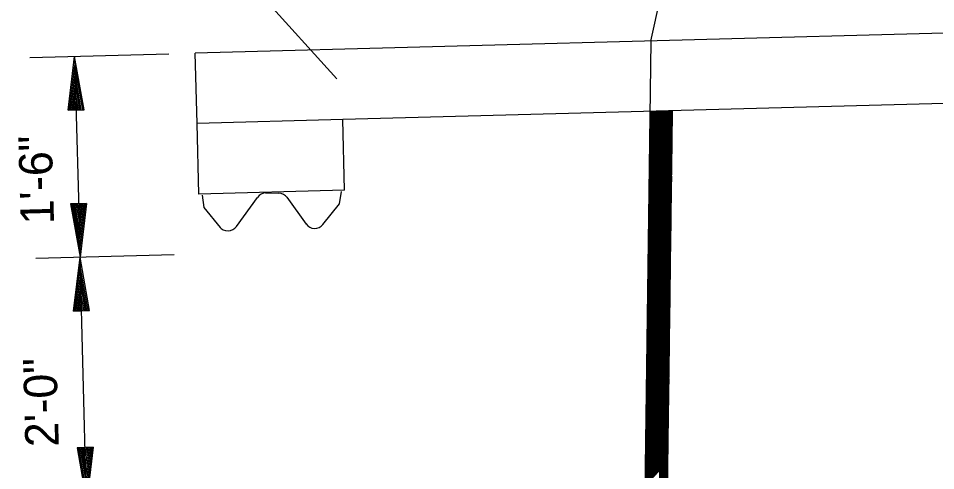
# Model space of a CAD drawing. Extents: x 1929624 to 1935547, y 596315 to 605721.
# Drawn here: x 1932251.9 to 1932416.4, y 600610.8 to 600691.9 of the extents above; entities that cross this region are included whole.
import ezdxf

# ---------------------------------------------------------------- set-up
doc = ezdxf.new("R2010")
doc.units = 0
doc.layers.add('Default', color=7, linetype='Continuous')

msp = doc.modelspace()

# ---------------------------------------------------------------- linework, layer by layer
at = {"layer": 'Default'}
for p, q in [((1932365.29, 600687.8), (1932409.04, 600885.31)), ((1932308.96, 600681.05), (1932287.75, 600704.49)), ((1932365.29, 600687.8), (1932362.18, 600451.38)), ((1932283.91, 600673.01), (1932283.58, 600685.61)), ((1932278.83, 600685.48), (1932253.92, 600684.81)), ((1932260.78, 600675.39), (1932261.96, 600685.03)), ((1932261.96, 600685.03), (1932262.93, 600649.04)), ((1932263.66, 600675.47), (1932261.96, 600685.03)), ((1932261.02, 600675.4), (1932262, 600683.45)), ((1932263.42, 600675.47), (1932262, 600683.45)), ((1932261.26, 600675.41), (1932262.05, 600681.79)), ((1932263.15, 600675.46), (1932262.05, 600681.79)), ((1932261.5, 600675.41), (1932262.09, 600680.18)), ((1932262.91, 600675.45), (1932262.09, 600680.18)), ((1932261.74, 600675.42), (1932262.13, 600678.55)), ((1932262.67, 600675.45), (1932262.13, 600678.55)), ((1932463.02, 600677.82), (1932310.04, 600673.72)), ((1932261.98, 600675.43), (1932262.18, 600676.97)), ((1932262.43, 600675.44), (1932262.18, 600676.97)), ((1932260.78, 600675.39), (1932263.66, 600675.47)), ((1932365.13, 600675.19), (1932366.85, 600610.85)), ((1932365.18, 600675.2), (1932366.9, 600610.9)), ((1932365.23, 600675.2), (1932366.95, 600610.96)), ((1932365.28, 600675.2), (1932367, 600611.01)), ((1932365.33, 600675.2), (1932367.05, 600611.06)), ((1932365.38, 600675.2), (1932367.1, 600611.11)), ((1932365.43, 600675.2), (1932367.14, 600611.17)), ((1932365.48, 600675.2), (1932367.19, 600611.22)), ((1932365.53, 600675.21), (1932367.24, 600611.27)), ((1932365.58, 600675.21), (1932367.29, 600611.32)), ((1932365.63, 600675.21), (1932367.34, 600611.38)), ((1932365.68, 600675.21), (1932367.39, 600611.43)), ((1932365.73, 600675.21), (1932367.44, 600611.48)), ((1932365.78, 600675.21), (1932367.48, 600611.53)), ((1932365.83, 600675.21), (1932367.53, 600611.59)), ((1932365.88, 600675.21), (1932367.58, 600611.64)), ((1932365.93, 600675.22), (1932367.63, 600611.69)), ((1932365.98, 600675.22), (1932367.68, 600611.74)), ((1932366.03, 600675.22), (1932367.73, 600611.8)), ((1932366.08, 600675.22), (1932367.78, 600611.85)), ((1932366.13, 600675.22), (1932367.82, 600611.9)), ((1932366.18, 600675.22), (1932367.87, 600611.95)), ((1932369.13, 600675.3), (1932366.19, 600451.33)), ((1932366.23, 600675.22), (1932367.92, 600612)), ((1932366.28, 600675.23), (1932367.97, 600612.06)), ((1932366.32, 600675.23), (1932368.02, 600612.11)), ((1932366.37, 600675.23), (1932368.07, 600612.16)), ((1932366.42, 600675.23), (1932368.12, 600612.21)), ((1932366.47, 600675.23), (1932368.17, 600612.27)), ((1932366.52, 600675.23), (1932368.21, 600612.32)), ((1932366.57, 600675.23), (1932368.26, 600612.37)), ((1932366.62, 600675.23), (1932368.31, 600612.52)), ((1932366.67, 600675.24), (1932368.32, 600613.77)), ((1932366.72, 600675.24), (1932368.34, 600615.02)), ((1932366.77, 600675.24), (1932368.36, 600616.27)), ((1932366.82, 600675.24), (1932368.37, 600617.53)), ((1932366.87, 600675.24), (1932368.39, 600618.78)), ((1932366.92, 600675.24), (1932368.41, 600620.03)), ((1932366.97, 600675.24), (1932368.42, 600621.28)), ((1932367.02, 600675.25), (1932368.44, 600622.53)), ((1932367.07, 600675.25), (1932368.46, 600623.78)), ((1932367.12, 600675.25), (1932368.47, 600625.03)), ((1932367.17, 600675.25), (1932368.49, 600626.28)), ((1932367.22, 600675.25), (1932368.51, 600627.53)), ((1932367.27, 600675.25), (1932368.52, 600628.78)), ((1932367.32, 600675.25), (1932368.54, 600630.04)), ((1932367.37, 600675.25), (1932368.55, 600631.29)), ((1932367.42, 600675.26), (1932368.57, 600632.54)), ((1932367.47, 600675.26), (1932368.59, 600633.79)), ((1932367.52, 600675.26), (1932368.6, 600635.04)), ((1932367.57, 600675.26), (1932368.62, 600636.29)), ((1932367.62, 600675.26), (1932368.64, 600637.54)), ((1932367.67, 600675.26), (1932368.65, 600638.79)), ((1932367.72, 600675.26), (1932368.67, 600640.04)), ((1932367.77, 600675.27), (1932368.69, 600641.3)), ((1932367.82, 600675.27), (1932368.7, 600642.55)), ((1932367.87, 600675.27), (1932368.72, 600643.8)), ((1932367.92, 600675.27), (1932368.74, 600645.05)), ((1932367.97, 600675.27), (1932368.75, 600646.3)), ((1932368.02, 600675.27), (1932368.77, 600647.55)), ((1932368.07, 600675.27), (1932368.78, 600648.8)), ((1932368.12, 600675.27), (1932368.8, 600650.05)), ((1932368.17, 600675.28), (1932368.82, 600651.3)), ((1932368.22, 600675.28), (1932368.83, 600652.55)), ((1932368.27, 600675.28), (1932368.85, 600653.81)), ((1932368.32, 600675.28), (1932368.87, 600655.06)), ((1932368.37, 600675.28), (1932368.88, 600656.31)), ((1932368.42, 600675.28), (1932368.9, 600657.56)), ((1932368.47, 600675.28), (1932368.92, 600658.81)), ((1932368.52, 600675.29), (1932368.93, 600660.06)), ((1932368.57, 600675.29), (1932368.95, 600661.31)), ((1932368.62, 600675.29), (1932368.97, 600662.56)), ((1932368.67, 600675.29), (1932368.98, 600663.81)), ((1932368.72, 600675.29), (1932369, 600665.07)), ((1932368.77, 600675.29), (1932369.02, 600666.32)), ((1932368.82, 600675.29), (1932369.03, 600667.57)), ((1932368.87, 600675.3), (1932369.05, 600668.82)), ((1932368.92, 600675.3), (1932369.06, 600670.07)), ((1932368.97, 600675.3), (1932369.08, 600671.32)), ((1932369.02, 600675.3), (1932369.1, 600672.57)), ((1932369.07, 600675.3), (1932369.11, 600673.82)), ((1932369.12, 600675.3), (1932369.13, 600675.07)), ((1932310.04, 600673.72), (1932283.91, 600673.01)), ((1932284.25, 600660.37), (1932283.91, 600673.01)), ((1932310.38, 600661.07), (1932310.04, 600673.72)), ((1932365.09, 600672.7), (1932366.76, 600610.75)), ((1932365.11, 600673.96), (1932366.8, 600610.8)), ((1932365.08, 600671.45), (1932366.71, 600610.69)), ((1932365.06, 600670.2), (1932366.66, 600610.64)), ((1932365.03, 600667.7), (1932366.56, 600610.54)), ((1932365.04, 600668.95), (1932366.61, 600610.59)), ((1932365.01, 600666.45), (1932366.51, 600610.49)), ((1932364.99, 600665.2), (1932366.46, 600610.43)), ((1932364.96, 600662.7), (1932366.37, 600610.33)), ((1932364.98, 600663.95), (1932366.42, 600610.38)), ((1932310.38, 600661.07), (1932284.25, 600660.37)), ((1932364.94, 600661.45), (1932366.32, 600610.28)), ((1932284.83, 600660.17), (1932285.16, 600657.99)), ((1932290.96, 600654.57), (1932294.74, 600659.76)), ((1932296.2, 600660.57), (1932298.56, 600660.54)), ((1932300.02, 600659.81), (1932303.46, 600655)), ((1932309.44, 600658.65), (1932309.79, 600660.82)), ((1932364.93, 600660.19), (1932366.27, 600610.22)), ((1932264.11, 600658.68), (1932261.23, 600658.6)), ((1932261.23, 600658.6), (1932262.93, 600649.04)), ((1932261.47, 600658.61), (1932262.88, 600650.65)), ((1932261.71, 600658.61), (1932262.84, 600652.31)), ((1932261.95, 600658.62), (1932262.8, 600653.89)), ((1932262.19, 600658.63), (1932262.75, 600655.52)), ((1932262.43, 600658.63), (1932262.71, 600657.13)), ((1932262.88, 600658.64), (1932262.71, 600657.13)), ((1932263.12, 600658.65), (1932262.75, 600655.52)), ((1932263.36, 600658.66), (1932262.8, 600653.89)), ((1932263.6, 600658.66), (1932262.84, 600652.31)), ((1932263.87, 600658.67), (1932262.88, 600650.65)), ((1932264.11, 600658.68), (1932262.93, 600649.04)), ((1932285.16, 600657.99), (1932288.04, 600654.4)), ((1932306.49, 600654.94), (1932309.44, 600658.65)), ((1932364.9, 600657.69), (1932366.17, 600610.12)), ((1932364.91, 600658.94), (1932366.22, 600610.17)), ((1932364.88, 600656.44), (1932366.12, 600610.07)), ((1932364.86, 600655.19), (1932366.07, 600610.01)), ((1932364.85, 600653.94), (1932366.03, 600609.96)), ((1932364.81, 600651.44), (1932365.93, 600609.86)), ((1932364.83, 600652.69), (1932365.98, 600609.91)), ((1932279.79, 600649.5), (1932255.01, 600648.83)), ((1932364.8, 600650.19), (1932365.88, 600609.8)), ((1932261.74, 600639.41), (1932262.93, 600649.04)), ((1932264.1, 600605.33), (1932262.93, 600649.04)), ((1932264.62, 600639.48), (1932262.93, 600649.04)), ((1932364.78, 600648.93), (1932365.83, 600609.75)), ((1932261.98, 600639.41), (1932262.97, 600647.44)), ((1932264.38, 600639.48), (1932262.97, 600647.44)), ((1932364.75, 600646.43), (1932365.73, 600609.65)), ((1932364.76, 600647.68), (1932365.78, 600609.7)), ((1932262.22, 600639.42), (1932263.01, 600645.78)), ((1932264.14, 600639.47), (1932263.01, 600645.78)), ((1932364.73, 600645.18), (1932365.69, 600609.59)), ((1932262.46, 600639.43), (1932263.06, 600644.2)), ((1932263.9, 600639.47), (1932263.06, 600644.2)), ((1932364.71, 600643.93), (1932365.64, 600609.54)), ((1932262.73, 600639.43), (1932263.1, 600642.56)), ((1932263.66, 600639.46), (1932263.1, 600642.56)), ((1932364.68, 600641.43), (1932365.54, 600609.44)), ((1932364.7, 600642.68), (1932365.59, 600609.49)), ((1932262.97, 600639.44), (1932263.14, 600640.96)), ((1932263.4, 600639.45), (1932263.14, 600640.96)), ((1932364.66, 600640.18), (1932365.49, 600609.39)), ((1932261.74, 600639.41), (1932264.62, 600639.48)), ((1932364.65, 600638.93), (1932365.44, 600609.33)), ((1932364.62, 600636.42), (1932365.35, 600609.23)), ((1932364.63, 600637.68), (1932365.39, 600609.28)), ((1932364.6, 600635.17), (1932365.3, 600609.18)), ((1932364.58, 600633.92), (1932365.25, 600609.12)), ((1932364.55, 600631.42), (1932365.15, 600609.02)), ((1932364.57, 600632.67), (1932365.2, 600609.07)), ((1932364.53, 600630.17), (1932365.1, 600608.97)), ((1932364.52, 600628.92), (1932365.05, 600608.91)), ((1932364.48, 600626.42), (1932364.96, 600608.81)), ((1932364.5, 600627.67), (1932365.01, 600608.86)), ((1932364.47, 600625.16), (1932364.91, 600608.76)), ((1932364.45, 600623.91), (1932364.86, 600608.7)), ((1932364.43, 600622.66), (1932364.81, 600608.65)), ((1932364.4, 600620.16), (1932364.71, 600608.55)), ((1932364.42, 600621.41), (1932364.76, 600608.6)), ((1932364.39, 600618.91), (1932364.67, 600608.49)), ((1932364.37, 600617.66), (1932364.62, 600608.44)), ((1932265.28, 600614.97), (1932262.4, 600614.89)), ((1932262.4, 600614.89), (1932264.1, 600605.33)), ((1932262.64, 600614.89), (1932264.06, 600606.94)), ((1932262.88, 600614.9), (1932264.01, 600608.59)), ((1932263.12, 600614.91), (1932263.97, 600610.18)), ((1932263.36, 600614.91), (1932263.93, 600611.81)), ((1932263.63, 600614.92), (1932263.88, 600613.42)), ((1932264.06, 600614.93), (1932263.88, 600613.42)), ((1932264.3, 600614.94), (1932263.93, 600611.81)), ((1932264.56, 600614.95), (1932263.97, 600610.18)), ((1932264.8, 600614.95), (1932264.01, 600608.59)), ((1932265.04, 600614.96), (1932264.06, 600606.94)), ((1932265.28, 600614.97), (1932264.1, 600605.33)), ((1932364.34, 600615.16), (1932364.52, 600608.34)), ((1932364.35, 600616.41), (1932364.57, 600608.39)), ((1932364.32, 600613.91), (1932364.47, 600608.28)), ((1932364.3, 600612.65), (1932364.42, 600608.23)), ((1932368.08, 600594.85), (1932367.63, 600611.59)), ((1932368.08, 600595.45), (1932367.65, 600611.61)), ((1932368.09, 600596.05), (1932367.67, 600611.64)), ((1932368.1, 600596.65), (1932367.7, 600611.66)), ((1932368.11, 600597.25), (1932367.72, 600611.69)), ((1932368.12, 600597.85), (1932367.74, 600611.71)), ((1932368.12, 600598.45), (1932367.77, 600611.74)), ((1932368.13, 600599.05), (1932367.79, 600611.76)), ((1932368.14, 600599.65), (1932367.81, 600611.79)), ((1932368.15, 600600.25), (1932367.84, 600611.81)), ((1932368.16, 600600.85), (1932367.86, 600611.84)), ((1932368.16, 600601.45), (1932367.88, 600611.86)), ((1932368.17, 600602.05), (1932367.91, 600611.89)), ((1932368.18, 600602.65), (1932367.93, 600611.91)), ((1932368.19, 600603.25), (1932367.95, 600611.93)), ((1932368.19, 600603.85), (1932367.98, 600611.96)), ((1932368.2, 600604.45), (1932368, 600611.98)), ((1932368.21, 600605.05), (1932368.02, 600612.01)), ((1932368.22, 600605.65), (1932368.05, 600612.03)), ((1932368.23, 600606.26), (1932368.07, 600612.06)), ((1932368.23, 600606.86), (1932368.09, 600612.08)), ((1932368.24, 600607.46), (1932368.12, 600612.11)), ((1932368.25, 600608.06), (1932368.14, 600612.13)), ((1932368.26, 600608.66), (1932368.16, 600612.16)), ((1932368.27, 600609.26), (1932368.19, 600612.18)), ((1932368.27, 600609.86), (1932368.21, 600612.21)), ((1932368.28, 600610.46), (1932368.23, 600612.23)), ((1932368.29, 600611.06), (1932368.26, 600612.25)), ((1932368.3, 600611.66), (1932368.28, 600612.28)), ((1932368.3, 600612.26), (1932368.3, 600612.3)), ((1932364.29, 600611.4), (1932364.37, 600608.18)), ((1932367.82, 600575.63), (1932366.88, 600610.8)), ((1932367.83, 600576.23), (1932366.9, 600610.83)), ((1932367.84, 600576.83), (1932366.93, 600610.85)), ((1932367.85, 600577.43), (1932366.95, 600610.88)), ((1932367.86, 600578.03), (1932366.97, 600610.9)), ((1932367.86, 600578.63), (1932367, 600610.92)), ((1932367.87, 600579.23), (1932367.02, 600610.95)), ((1932367.88, 600579.83), (1932367.04, 600610.97)), ((1932367.89, 600580.43), (1932367.07, 600611)), ((1932367.89, 600581.03), (1932367.09, 600611.02)), ((1932367.9, 600581.64), (1932367.11, 600611.05)), ((1932367.91, 600582.24), (1932367.14, 600611.07)), ((1932367.92, 600582.84), (1932367.16, 600611.1)), ((1932367.93, 600583.44), (1932367.18, 600611.12)), ((1932367.93, 600584.04), (1932367.21, 600611.15)), ((1932367.94, 600584.64), (1932367.23, 600611.17)), ((1932367.95, 600585.24), (1932367.25, 600611.2)), ((1932367.96, 600585.84), (1932367.28, 600611.22)), ((1932367.97, 600586.44), (1932367.3, 600611.24)), ((1932367.97, 600587.04), (1932367.32, 600611.27)), ((1932367.98, 600587.64), (1932367.35, 600611.29)), ((1932367.99, 600588.24), (1932367.37, 600611.32)), ((1932368, 600588.84), (1932367.39, 600611.34)), ((1932368.01, 600589.44), (1932367.42, 600611.37)), ((1932368.01, 600590.04), (1932367.44, 600611.39)), ((1932368.02, 600590.64), (1932367.46, 600611.42)), ((1932368.03, 600591.24), (1932367.49, 600611.44)), ((1932368.04, 600591.84), (1932367.51, 600611.47)), ((1932368.04, 600592.45), (1932367.53, 600611.49)), ((1932368.05, 600593.05), (1932367.56, 600611.52)), ((1932368.06, 600593.65), (1932367.58, 600611.54)), ((1932368.07, 600594.25), (1932367.6, 600611.56))]:
    msp.add_line(p, q, dxfattribs=at)
msp.add_lwpolyline([(1932463.02, 600677.82), (1932462.68, 600690.42), (1932283.58, 600685.61)], dxfattribs=at)
for centre, start, end in [((1932296.28, 600658.67), 89.1517, 143.9947), ((1932298.52, 600658.64), 35.653, 89.1961), ((1932289.43, 600655.7), 218.6962, 323.9765), ((1932305, 600656.12), 215.6908, 321.5912)]:
    msp.add_arc(centre, 1.9, start, end, dxfattribs=at)

# ---------------------------------------------------------------- texts
for s, p in [('1\'-6"', (1932258.28, 600655)), ('2\'-0"', (1932259.13, 600615.12))]:
    msp.add_text(s, height=6, rotation=91.5377, dxfattribs=at).set_placement(p)

doc.saveas('drawing.dxf')
